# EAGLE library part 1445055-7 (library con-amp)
Micro MATE-N-LOK Connectors grid 1.5 mm Source: ENG_CD_1445055_A.pdf
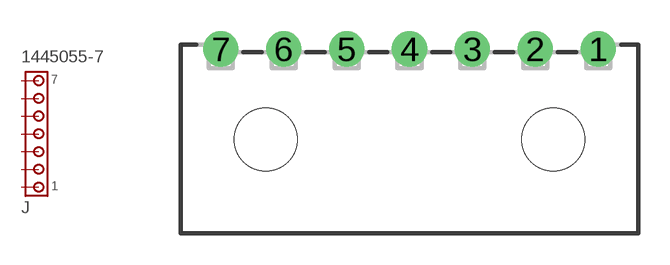
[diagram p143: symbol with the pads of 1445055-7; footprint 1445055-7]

Designator prefix J

## 1445055-7 (MPN: 2-1445055-7; OC_FARNELL: unknown; OC_NEWARK: 17R5936)  [1445055-7]
1  1  pas
2  2  pas
3  3  pas
4  4  pas
5  5  pas
6  6  pas
7  7  pas

## Footprint 1445055-7 (pad centres in mm)
Micro MATE-N-LOK Connectors grid 3.0 mm Source: ENG_CD_1445055_A.pdf
drill 1 pad 1.676 round: 1 9,4.32; 2 6,4.32; 3 3,4.32; 4 0,4.32; 5 -3,4.32; 6 -6,4.32; 7 -9,4.32
hole 3 at -6.85,0
hole 3 at 6.85,0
